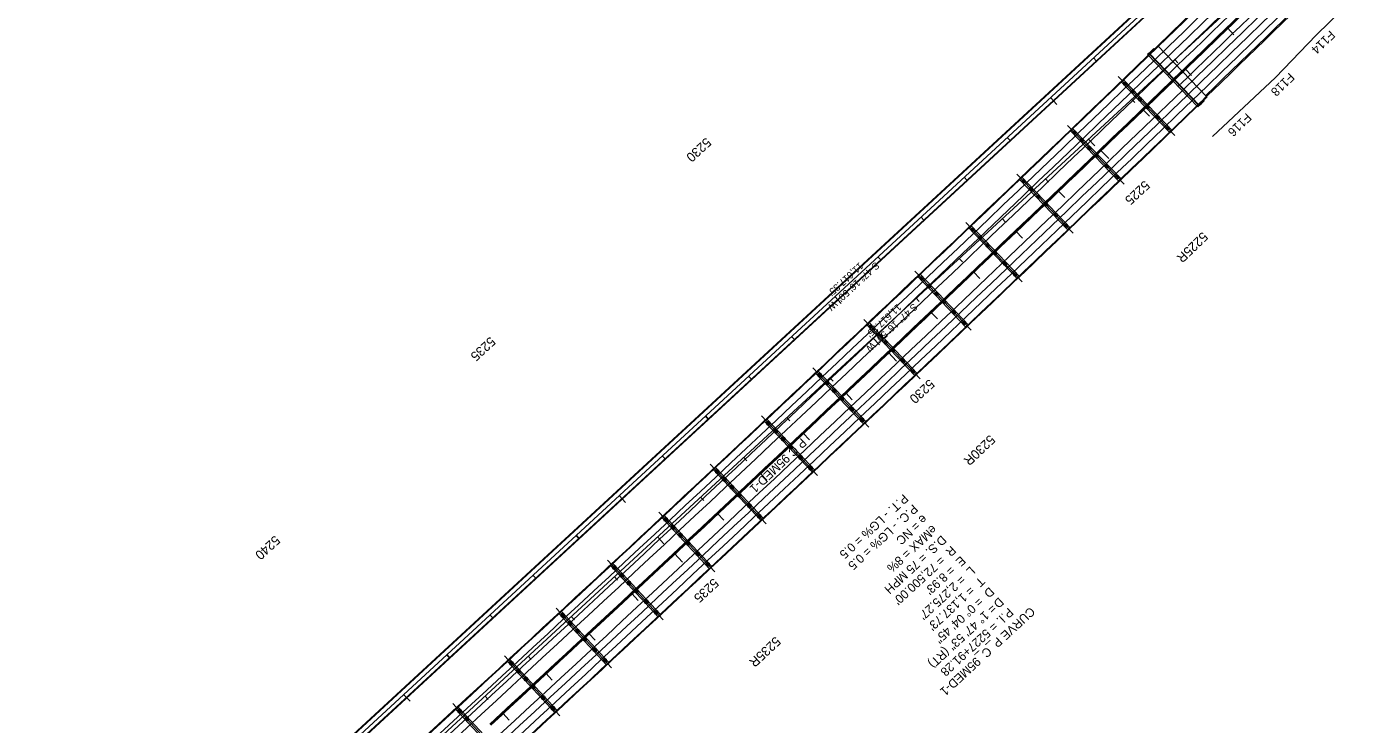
# Model space of a CAD drawing. Extents: x 2160877 to 2175861, y 601747 to 617724.
# Drawn here: x 2166538 to 2168832, y 609082 to 610271 of the extents above; entities that cross this region are included whole.
import ezdxf

# ---------------------------------------------------------------- set-up
doc = ezdxf.new("R2010")
doc.units = 0
for name, color, linetype in [('BR_CENTER LINES', 7, 'Continuous'), ('BR_CONCRETE', 7, 'Continuous'), ('RD_HC_Cl', 7, 'Continuous'), ('RD_HC_CL_Rel', 7, 'Continuous'), ('RD_HC_Data_Rel', 7, 'Continuous'), ('RD_HC_Data_Tic', 7, 'Continuous'), ('RD_HC_Data_Tic_Rel', 7, 'Continuous'), ('RD_HC_TX_Rel_Sta50', 7, 'Continuous'), ('RD_HC_TX_StaOther', 7, 'Continuous'), ('RD_PD_CstnLmt', 7, 'Continuous'), ('RD_PD_CstnLmt_TX', 7, 'Continuous'), ('RD_PD_Final_LnLine', 7, 'Continuous'), ('RD_PD_Final_TrvlWay', 7, 'Continuous'), ('RD_PD_GR', 7, 'Continuous'), ('RD_PD_MedBWall', 7, 'Continuous')]:
    doc.layers.add(name, color=color, linetype=linetype)

msp = doc.modelspace()

# ---------------------------------------------------------------- linework, layer by layer
at = {"layer": 'BR_CENTER LINES'}
for p, q in [((2168397.6, 610186.4), (2168494.3, 610086.1)), ((2168311.2, 610103.3), (2168407.7, 610002.8)), ((2168224.7, 610020.3), (2168321, 609919.7)), ((2168138, 609937.5), (2168234.2, 609836.7)), ((2168051.2, 609854.8), (2168147.2, 609753.9)), ((2167964.2, 609772.3), (2168060.1, 609671.2)), ((2167877.2, 609689.9), (2167972.8, 609588.6)), ((2167789.9, 609607.7), (2167885.4, 609506.2)), ((2167702.6, 609525.6), (2167797.9, 609423.9)), ((2167615.1, 609443.6), (2167710.2, 609341.8)), ((2167527.4, 609361.8), (2167622.4, 609259.9)), ((2167439.7, 609280.1), (2167534.5, 609178)), ((2167351.8, 609198.6), (2167446.4, 609096.4)), ((2167263.7, 609117.2), (2167358.3, 609014.8))]:
    msp.add_line(p, q, dxfattribs=at)
at = {"layer": 'BR_CONCRETE'}
for p, q in [((2168458.5, 610234.3), (2168459.6, 610233.2)), ((2168465.3, 610238.6), (2168549, 610151.9)), ((2168447.8, 610223.9), (2168533.7, 610134.9)), ((2168450.3, 610226.3), (2168536.2, 610137.3)), ((2168450.8, 610224.8), (2168534.7, 610137.9)), ((2168543.4, 610146.4), (2168544.5, 610145.3)), ((2167286.8, 609125.7), (2166009.5, 607946.3)), ((2167286.8, 609125.6), (2166009.6, 607946.2)), ((2167287.5, 609124.9), (2166010.3, 607945.5))]:
    msp.add_line(p, q, dxfattribs=at)
for points in [[(2168406.5, 610181.1), (2168402.6, 610177.3), (2168485.4, 610091.4), (2168489.3, 610095.2)], [(2168320.1, 610098), (2168316.2, 610094.2), (2168398.8, 610008.1), (2168402.8, 610011.9)], [(2168233.6, 610015), (2168229.6, 610011.2), (2168312.1, 609925), (2168316.1, 609928.8)], [(2168146.9, 609932.2), (2168142.9, 609928.4), (2168225.3, 609842), (2168229.3, 609845.8)], [(2168060.1, 609849.5), (2168056.1, 609845.7), (2168138.3, 609759.2), (2168142.3, 609763)], [(2167973.1, 609766.9), (2167969.1, 609763.1), (2168051.2, 609676.5), (2168055.2, 609680.3)], [(2167886, 609684.5), (2167882, 609680.7), (2167964, 609594), (2167968, 609597.8)], [(2167798.8, 609602.3), (2167794.8, 609598.5), (2167876.6, 609511.6), (2167880.6, 609515.4)], [(2167711.4, 609520.1), (2167707.4, 609516.4), (2167789.1, 609429.4), (2167793.1, 609433.1)], [(2167623.9, 609438.2), (2167619.9, 609434.4), (2167701.4, 609347.3), (2167705.4, 609351)], [(2167536.3, 609356.3), (2167532.3, 609352.6), (2167613.6, 609265.3), (2167617.6, 609269.1)], [(2167448.5, 609274.7), (2167444.5, 609270.9), (2167525.7, 609183.5), (2167529.7, 609187.2)], [(2167360.6, 609193.1), (2167356.6, 609189.4), (2167437.6, 609101.8), (2167441.7, 609105.6)], [(2167272.5, 609111.7), (2167268.5, 609108), (2167349.5, 609020.3), (2167353.5, 609024)]]:
    msp.add_lwpolyline(points, close=True, dxfattribs=at)
for centre, radius in [((2168409.5, 610174.1), 2.5), ((2168422.2, 610160.9), 2.5), ((2168434.9, 610147.7), 2.5), ((2168447.6, 610134.5), 2.5), ((2168465, 610116.5), 2.5), ((2168482.3, 610098.5), 2.5), ((2168323.1, 610091), 2.5), ((2168335.8, 610077.8), 2.5), ((2168348.5, 610064.5), 2.5), ((2168361.1, 610051.3), 2.5), ((2168378.5, 610033.3), 2.5), ((2168236.5, 610008), 2.5), ((2168395.8, 610015.2), 2.5), ((2168249.2, 609994.7), 2.5), ((2168261.8, 609981.5), 2.5), ((2168274.5, 609968.3), 2.5), ((2168291.8, 609950.2), 2.5), ((2168309.1, 609932.1), 2.5), ((2168149.8, 609925.1), 2.5), ((2168162.5, 609911.9), 2.5), ((2168175.1, 609898.6), 2.5), ((2168187.8, 609885.4), 2.5), ((2168205, 609867.3), 2.5), ((2168063, 609842.4), 2.5), ((2168222.3, 609849.2), 2.5), ((2168075.6, 609829.2), 2.5), ((2168088.2, 609815.9), 2.5), ((2168100.9, 609802.6), 2.5), ((2168118.1, 609784.5), 2.5), ((2167976, 609759.9), 2.5), ((2168135.3, 609766.4), 2.5), ((2167988.6, 609746.6), 2.5), ((2168001.2, 609733.3), 2.5), ((2168013.8, 609720), 2.5), ((2168031, 609701.8), 2.5), ((2168048.2, 609683.7), 2.5), ((2167888.9, 609677.5), 3), ((2167888.9, 609677.5), 2), ((2167901.5, 609664.2), 3), ((2167901.5, 609664.2), 2), ((2167914.1, 609650.8), 3), ((2167914.1, 609650.8), 2), ((2167926.7, 609637.5), 3), ((2167926.7, 609637.5), 2), ((2167943.8, 609619.3), 3), ((2167943.8, 609619.3), 2), ((2167801.6, 609595.2), 3), ((2167801.6, 609595.2), 2), ((2167961, 609601.2), 3), ((2167961, 609601.2), 2), ((2167814.2, 609581.9), 3), ((2167814.2, 609581.9), 2), ((2167826.8, 609568.5), 3), ((2167826.8, 609568.5), 2), ((2167839.3, 609555.2), 3), ((2167839.3, 609555.2), 2), ((2167856.5, 609537), 3), ((2167856.5, 609537), 2), ((2167873.6, 609518.8), 3), ((2167873.6, 609518.8), 2), ((2167714.3, 609513.1), 3), ((2167714.3, 609513.1), 2), ((2167726.8, 609499.7), 3), ((2167726.8, 609499.7), 2), ((2167739.4, 609486.4), 3), ((2167739.4, 609486.4), 2), ((2167751.9, 609473), 3), ((2167751.9, 609473), 2), ((2167769, 609454.8), 3), ((2167769, 609454.8), 2), ((2167626.7, 609431.1), 3), ((2167626.7, 609431.1), 2), ((2167786.1, 609436.5), 3), ((2167786.1, 609436.5), 2), ((2167639.3, 609417.7), 3), ((2167639.3, 609417.7), 2), ((2167651.8, 609404.3), 3), ((2167651.8, 609404.3), 2), ((2167664.3, 609390.9), 3), ((2167664.3, 609390.9), 2), ((2167681.4, 609372.7), 3), ((2167681.4, 609372.7), 2), ((2167539.1, 609349.3), 3), ((2167539.1, 609349.3), 2), ((2167551.6, 609335.9), 3), ((2167551.6, 609335.9), 2), ((2167698.5, 609354.4), 3), ((2167698.5, 609354.4), 2), ((2167564.1, 609322.5), 3), ((2167564.1, 609322.5), 2), ((2167576.6, 609309.1), 3), ((2167576.6, 609309.1), 2), ((2167593.6, 609290.8), 3), ((2167593.6, 609290.8), 2), ((2167451.3, 609267.6), 3), ((2167451.3, 609267.6), 2), ((2167610.7, 609272.5), 3), ((2167610.7, 609272.5), 2), ((2167463.8, 609254.2), 3), ((2167463.8, 609254.2), 2), ((2167476.3, 609240.7), 3), ((2167476.3, 609240.7), 2), ((2167488.7, 609227.3), 3), ((2167488.7, 609227.3), 2), ((2167505.8, 609209), 3), ((2167505.8, 609209), 2), ((2167363.4, 609186.1), 3), ((2167363.4, 609186.1), 2), ((2167522.8, 609190.7), 3), ((2167522.8, 609190.7), 2), ((2167375.8, 609172.6), 3), ((2167375.8, 609172.6), 2), ((2167388.3, 609159.2), 3), ((2167388.3, 609159.2), 2), ((2167400.8, 609145.7), 3), ((2167400.8, 609145.7), 2), ((2167417.7, 609127.4), 3), ((2167275.3, 609104.7), 3), ((2167417.7, 609127.4), 2), ((2167434.7, 609109), 3), ((2167434.7, 609109), 2), ((2167275.3, 609104.7), 2), ((2167287.8, 609091.2), 3), ((2167287.8, 609091.2), 2)]:
    msp.add_circle(centre, radius, dxfattribs=at)
for centre, radius, start, end in [((2118143, 662346), 72439.7, 312.719474, 314.001574), ((2118143, 662346), 72439.8, 312.719474, 314.001574), ((2118143, 662346), 72440.8, 312.719474, 314.001574), ((2118144.8, 662347.8), 72438.1, 313.981475, 313.99334), ((2118144.8, 662347.8), 72439.6, 313.983716, 313.99334), ((2118143, 662346), 72498.8, 312.719474, 314.001574), ((2118143, 662346), 72501.2, 312.719474, 314.001574), ((2118143, 662346), 72559.2, 312.719474, 314.001574), ((2118143, 662346), 72560.2, 312.719474, 314.001574), ((2118143, 662346), 72560.3, 312.719474, 314.001574), ((2118144.8, 662347.8), 72561.9, 313.981479, 313.993323), ((2118144.8, 662347.8), 72560.4, 313.983716, 313.993323)]:
    msp.add_arc(centre, radius, start, end, dxfattribs=at)
at = {"layer": 'RD_HC_Cl'}
for p, q in [((2172207.3, 613775.1), (2163672.2, 605893.8)), ((2172272.5, 613704.6), (2163737.4, 605823.3))]:
    msp.add_line(p, q, dxfattribs=at)
at = {"layer": 'RD_HC_CL_Rel'}
msp.add_arc((2118143, 662346), 72500, 312.719474, 314.517591, dxfattribs=at)
at = {"layer": 'RD_HC_Data_Tic'}
for p, q in [((2168355.5, 610218.4), (2168360.9, 610212.5)), ((2168494.1, 610215.7), (2168499.5, 610209.8)), ((2168282.1, 610150.5), (2168292.9, 610138.8)), ((2168420.6, 610147.8), (2168426.1, 610142)), ((2168208.6, 610082.7), (2168214, 610076.8)), ((2168347.2, 610080), (2168358, 610068.3)), ((2168135.1, 610014.9), (2168140.5, 610009)), ((2168273.7, 610012.2), (2168279.1, 610006.3)), ((2168061.6, 609947), (2168067.1, 609941.1)), ((2168200.2, 609944.3), (2168205.7, 609938.4)), ((2167988.2, 609879.2), (2167993.6, 609873.3)), ((2168126.8, 609876.5), (2168132.2, 609870.6)), ((2167914.7, 609811.3), (2167925.6, 609799.6)), ((2168053.3, 609808.6), (2168058.7, 609802.8)), ((2167841.2, 609743.5), (2167846.7, 609737.6)), ((2167979.8, 609740.8), (2167990.7, 609729)), ((2167767.8, 609675.6), (2167773.2, 609669.8)), ((2167906.4, 609673), (2167911.8, 609667.1)), ((2167694.3, 609607.8), (2167699.7, 609601.9)), ((2167832.9, 609605.1), (2167838.3, 609599.2)), ((2167620.8, 609540), (2167626.3, 609534.1)), ((2167759.4, 609537.3), (2167764.9, 609531.4)), ((2167547.4, 609472.1), (2167558.2, 609460.4)), ((2167686, 609469.4), (2167691.4, 609463.6)), ((2167473.9, 609404.3), (2167479.3, 609398.4)), ((2167612.5, 609401.6), (2167623.4, 609389.8)), ((2167400.4, 609336.4), (2167405.9, 609330.6)), ((2167539, 609333.8), (2167544.5, 609327.9)), ((2167327, 609268.6), (2167332.4, 609262.7)), ((2167465.6, 609265.9), (2167471, 609260)), ((2167253.5, 609200.8), (2167258.9, 609194.9)), ((2167392.1, 609198.1), (2167397.5, 609192.2)), ((2167180, 609132.9), (2167190.9, 609121.2)), ((2167318.6, 609130.2), (2167324.1, 609124.4))]:
    msp.add_line(p, q, dxfattribs=at)
at = {"layer": 'RD_HC_Data_Tic_Rel'}
for p, q in [((2168583.7, 610269.3), (2168594.8, 610257.8)), ((2168511.8, 610199.8), (2168522.9, 610188.3)), ((2168439.8, 610130.3), (2168450.9, 610118.8)), ((2168367.8, 610061), (2168381.6, 610046.6)), ((2168295.6, 609991.8), (2168306.7, 609980.2)), ((2168223.3, 609922.7), (2168234.4, 609911.1)), ((2168151, 609853.6), (2168162, 609842)), ((2168078.5, 609784.7), (2168089.6, 609773.1)), ((2168006, 609715.9), (2168019.7, 609701.4)), ((2167933.4, 609647.2), (2167944.3, 609635.5)), ((2167860.6, 609578.5), (2167871.6, 609566.9)), ((2167787.8, 609510), (2167798.7, 609498.3)), ((2167714.9, 609441.6), (2167725.8, 609429.9)), ((2167641.8, 609373.3), (2167655.5, 609358.6)), ((2167568.7, 609305), (2167579.6, 609293.3)), ((2167495.5, 609236.9), (2167506.4, 609225.2)), ((2167422.2, 609168.9), (2167433.1, 609157.1)), ((2167348.8, 609101), (2167359.7, 609089.2))]:
    msp.add_line(p, q, dxfattribs=at)
at = {"layer": 'RD_PD_CstnLmt'}
for p, q in [((2168806.6, 610327), (2168735.1, 610256.9)), ((2168735.1, 610256.9), (2168665.8, 610184.6)), ((2168665.8, 610184.6), (2168558.5, 610084.1))]:
    msp.add_line(p, q, dxfattribs=at)
at = {"layer": 'RD_PD_Final_LnLine'}
for p, q in [((2166018.4, 607936.7), (2167295.7, 609116.1)), ((2166026.6, 607927.8), (2167303.8, 609107.2)), ((2166034.7, 607919), (2167311.9, 609098.4))]:
    msp.add_line(p, q, dxfattribs=at)
for radius in [72452.8, 72464.8, 72476.8, 72498.8, 72501.2, 72523.2, 72535.2, 72547.2]:
    msp.add_arc((2118143, 662346), radius, 312.719474, 314.517591, dxfattribs=at)
at = {"layer": 'RD_PD_Final_TrvlWay'}
msp.add_line((2168465.3, 610238.6), (2168608.1, 610378.6), dxfattribs=at)
for centre, radius, start in [((2118141.6, 662347.5), 72442.8, 314.001538), ((2118143, 662346), 72486.8, 313.983529), ((2118143, 662346), 72513.2, 313.98353), ((2118143, 662346), 72557.2, 314.001574)]:
    msp.add_arc(centre, radius, start, 314.517591, dxfattribs=at)
at = {"layer": 'RD_PD_GR'}
msp.add_arc((2118143, 662346), 72559.2, 313.996755, 314.517591, dxfattribs=at)
at = {"layer": 'RD_PD_MedBWall'}
for p, q in [((2169697.9, 611469.1), (2165055.7, 607182.5)), ((2169698.6, 611468.4), (2165056.4, 607181.7)), ((2169708.3, 611458.3), (2165065.8, 607171.5)), ((2169684.4, 611434.9), (2165066.5, 607170.7))]:
    msp.add_line(p, q, dxfattribs=at)

# ---------------------------------------------------------------- texts
at = {"layer": 'RD_HC_Data_Rel'}
for s, rotation, p in [('P C 95MED-1', 223.5528, (2167858, 609570.9)), ('P.T. - LG% = 0.5', 222.7195, (2168031.6, 609475.6)), ('P.C. - LG% = 0.5', 222.7195, (2168047.9, 609458)), ('e = NC', 222.7195, (2168064.1, 609440.3)), ('eMAX = 8%', 222.7195, (2168080.4, 609422.7)), ('D.S. = 75 MPH', 222.7195, (2168096.7, 609405.1)), ("R  = 72,500.00'", 222.7195, (2168113, 609387.4)), ("E  = 8.93'", 222.7195, (2168129.3, 609369.8)), ("L  = 2,275.27'", 222.7195, (2168145.6, 609352.2)), ("T  = 1,137.73'", 222.7195, (2168161.8, 609334.5)), ('D  = 0%%d 04\' 45"', 222.7195, (2168178.1, 609316.9)), ('D ', 222.7195, (2168194.4, 609299.3)), ('   = 1%%d 47\' 53" (RT)', 222.7195, (2168194.4, 609299.3)), ('CURVE P_C_95MED-1', 222.7195, (2168247.6, 609283)), ('P.I. = 5227+91.28', 222.7195, (2168210.7, 609281.6))]:
    msp.add_text(s, height=15, rotation=rotation, dxfattribs=at).set_placement(p)
at = {"layer": 'RD_HC_TX_Rel_Sta50'}
for s, rotation, p in [('5225R', 223.8487, (2168541.4, 609922.7)), ('5230R', 223.4535, (2168178.9, 609576.6)), ('5235R', 223.0584, (2167813.5, 609232.6))]:
    msp.add_text(s, height=16, rotation=rotation, dxfattribs=at).set_placement(p)
at = {"layer": 'RD_HC_TX_StaOther'}
for s, height, p in [('5230', 16, (2167695.2, 610083.4)), ('5225', 16, (2168442.7, 610010.3)), ('S 47%%d 16\' 50" W', 12, (2167984, 609871.2)), ("11,617.35'", 12, (2167956.6, 609870.4)), ('S 47%%d 16\' 50" W', 12, (2168049.1, 609800.7)), ("11,617.35'", 12, (2168021.7, 609799.9)), ('5235', 16, (2167327.5, 609743.9)), ('5230', 16, (2168075.7, 609671.4)), ('5240', 16, (2166960.5, 609405)), ('5235', 16, (2167708, 609331.9))]:
    msp.add_text(s, height=height, rotation=222.7195, dxfattribs=at).set_placement(p)
at = {"layer": 'RD_PD_CstnLmt_TX'}
for s, rotation, p in [('F114', 224.1648, (2168758.5, 610266.2)), ('F118', 224.0857, (2168689.4, 610194)), ('F116', 224.0067, (2168616.1, 610125.4))]:
    msp.add_text(s, height=15, rotation=rotation, dxfattribs=at).set_placement(p)

doc.saveas('drawing.dxf')
